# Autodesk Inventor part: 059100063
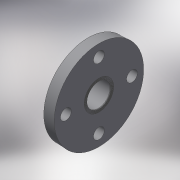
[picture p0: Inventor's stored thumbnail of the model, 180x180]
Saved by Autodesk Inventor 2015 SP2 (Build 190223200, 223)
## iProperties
Created: 2017-10
Part Number: 059100063
Material: Generic
Description: PLASSON FIXED FLANGE-CEM PVC 63
Document SubType Name: Modeling
Designer: KIM
Density: 1 g/cm^3
Appearance: Default
Author: KIM
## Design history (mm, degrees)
derived "059200.ipt"
feature "Solid1::059200.ipt"
tag "TaggingFeature1"
body "Solid1"
other parameters: "d0" = 39, "d2" = 165, "d3" = 163.35, "d14" = 18, "d15" = 62.5, "d16" = 39, "d17" = 0, "d19" = 360 deg, "d21" = 38, "d22" = 63, "d23" = 59.85, "d24" = 75.6, "d25" = 0.63, "d26" = 0.825, "d27" = 0.825, "d28" = 0.825, "d29" = 0.825, "d30" = 0.825, "d31" = 0.825, "d32" = 0.33, "d33" = 0, "d34" = 18, "E_" = 165, "H_" = 39, "Dp_" = 125, "S_" = 18, "l_" = 38, "d_" = 63, "H_1" = 18
